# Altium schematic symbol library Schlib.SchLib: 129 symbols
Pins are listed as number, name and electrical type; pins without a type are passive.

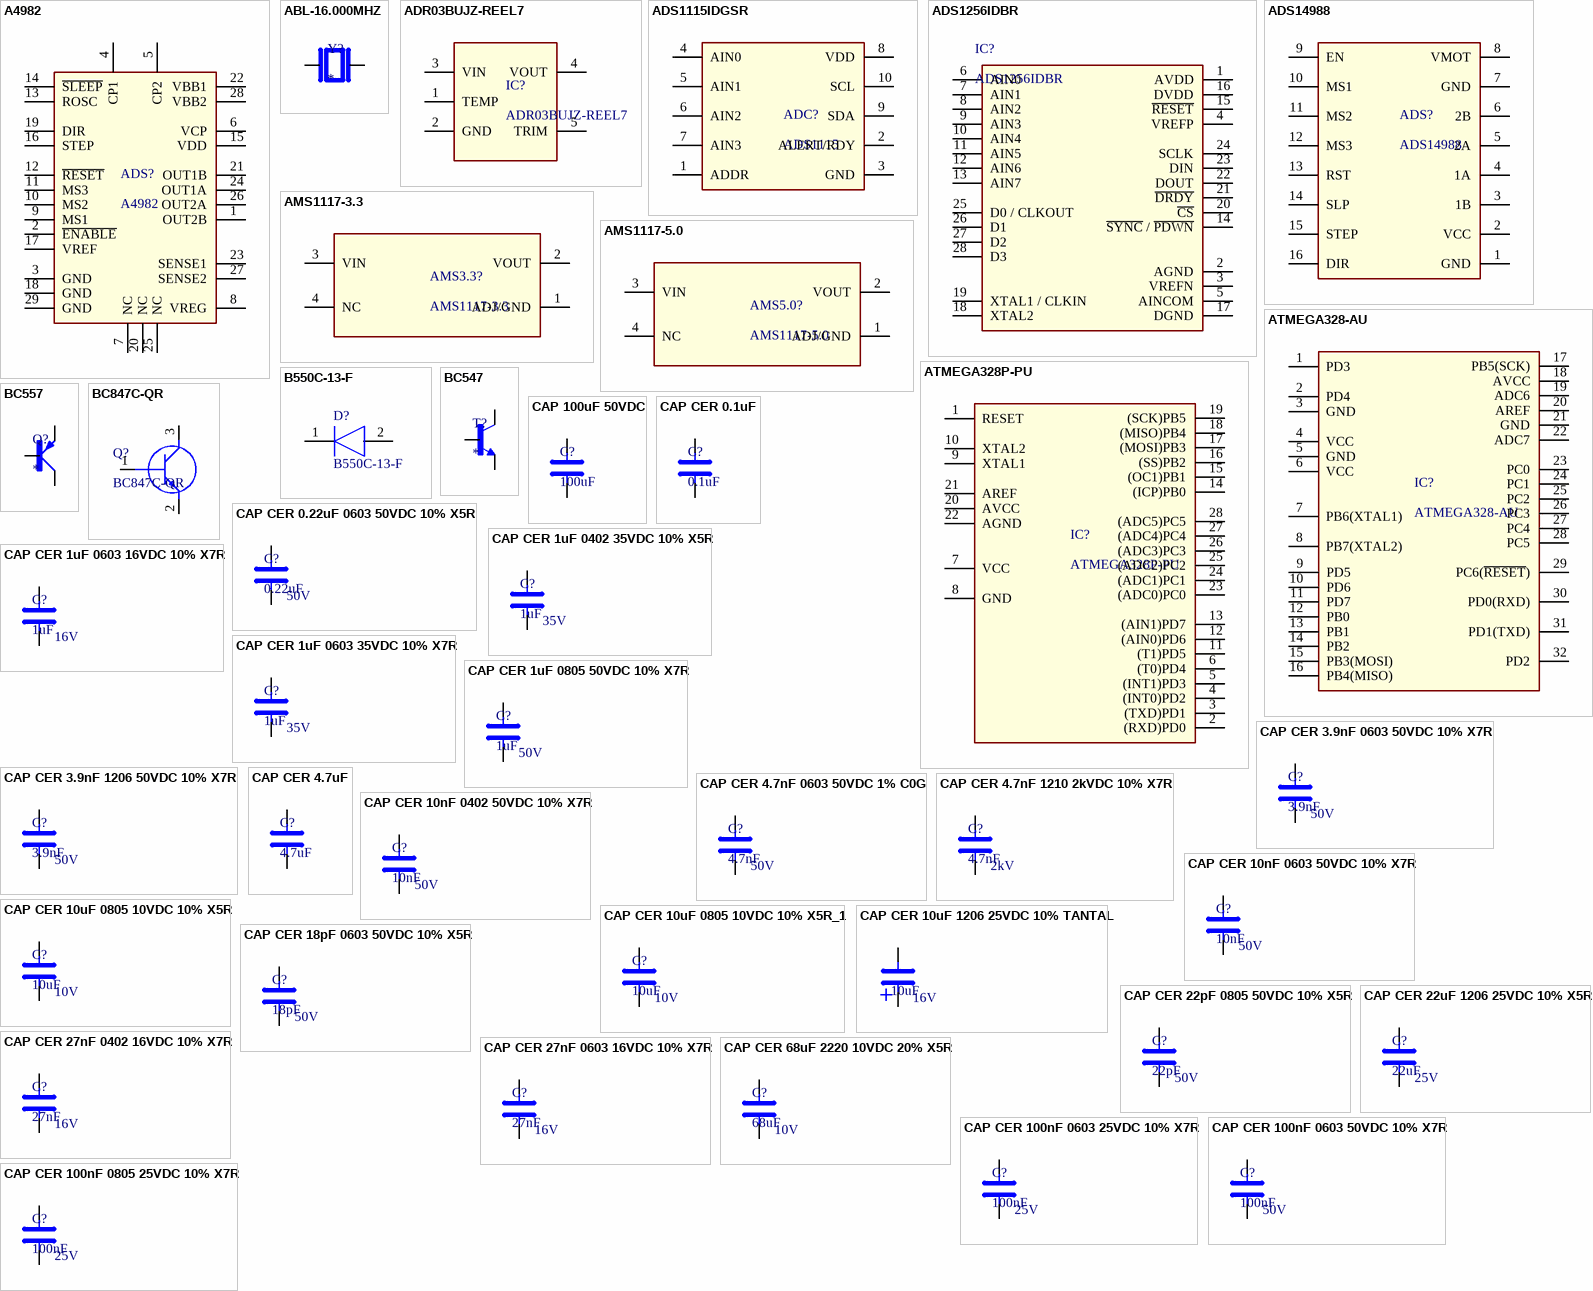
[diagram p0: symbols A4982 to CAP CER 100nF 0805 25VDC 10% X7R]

## A4982
designator ADS?
footprint QFN50P500X500X90-29N
pins: 1 OUT2B, 2 ~{ENABLE}, 3 GND, 4 CP1, 5 CP2, 6 VCP, 7 NC, 8 VREG, 9 MS1, 10 MS2, 11 MS3, 12 ~{RESET}, 13 ROSC, 14 ~{SLEEP}, 15 VDD, 16 STEP, 17 VREF, 18 GND, 19 DIR, 20 NC, 21 OUT1B, 22 VBB1, 23 SENSE1, 24 OUT1A, 25 NC, 26 OUT2A, 27 SENSE2, 28 VBB2, 29 GND

## ABL-16.000MHZ
designator Y?
16 MHz Â±10ppm Crystal 18pF 40 Ohms HC-49/US; MF: Abracon Corporation; MP: ABL-16.000MHZ
footprint XTAL_ABL-16.000MHZ
pins: 1, 2

## ADR03BUJZ-REEL7
designator IC?
2.5V -40℃~+125℃@(TA) ±0.1% 4.5V~36V 10mA 9ppm/℃ Fixed TSOT-23-5 Voltage References ROHS; Manufacturer: Analog Devices
footprint SON65P200X200X80-5N (ADR03BUJZ-REEL7)
pins: 1 TEMP, 2 GND, 3 VIN, 4 VOUT, 5 TRIM

## ADS1115IDGSR
designator ADC?, comment ADS1115
VSSOP-10 Analog To Digital Converters (ADCs) ROHS; Manufacturer: Texas Instruments; Manufacturer Part Number: ADS1115IDGSR
footprint SOP50P490X110-10N
pins: 1 ADDR, 2 ALERT/RDY, 3 GND, 4 AIN0, 5 AIN1, 6 AIN2, 7 AIN3, 8 VDD, 9 SDA, 10 SCL

## ADS1256IDBR
designator IC?
SSOP-28_208mil Analog To Digital Converters (ADCs) ROHS; Manufacturer: Texas Instruments
footprint SOP65P780X200-28N
pins: 1 AVDD, 2 AGND, 3 VREFN, 4 VREFP, 5 AINCOM, 6 AIN0, 7 AIN1, 8 AIN2, 9 AIN3, 10 AIN4, 11 AIN5, 12 AIN6, 13 AIN7, 14 ~{SYNC} / ~{PDWN}, 15 ~{RESET}, 16 DVDD, 17 DGND, 18 XTAL2, 19 XTAL1 / CLKIN, 20 ~{CS}, 21 ~{DRDY}, 22 DOUT, 23 DIN, 24 SCLK, 25 D0 / CLKOUT, 26 D1, 27 D2, 28 D3

## ADS14988
designator ADS?
pins: 1 GND, 2 VCC, 3 1B, 4 1A, 5 2A, 6 2B, 7 GND, 8 VMOT, 9 EN, 10 MS1, 11 MS2, 12 MS3, 13 RST, 14 SLP, 15 STEP, 16 DIR

## AMS1117-3.3
designator AMS3.3?
pins: 1 ADJ/GND, 2 VOUT, 3 VIN, 4 NC

## AMS1117-5.0
designator AMS5.0?
pins: 1 ADJ/GND, 2 VOUT, 3 VIN, 4 NC

## ATMEGA328-AU
designator IC?
footprint QFP80P900X900X120-32N
pins: 1 PD3, 2 PD4, 3 GND, 4 VCC, 5 GND, 6 VCC, 7 PB6(XTAL1), 8 PB7(XTAL2), 9 PD5, 10 PD6, 11 PD7, 12 PB0, 13 PB1, 14 PB2, 15 PB3(MOSI), 16 PB4(MISO), 17 PB5(SCK), 18 AVCC, 19 ADC6, 20 AREF, 21 GND, 22 ADC7, 23 PC0, 24 PC1, 25 PC2, 26 PC3, 27 PC4, 28 PC5, 29 PC6(~{RESET}), 30 PD0(RXD), 31 PD1(TXD), 32 PD2

## ATMEGA328P-PU
designator IC?
pins: 1 RESET, 2 (RXD)PD0, 3 (TXD)PD1, 4 (INT0)PD2, 5 (INT1)PD3, 6 (T0)PD4, 7 VCC, 8 GND, 9 XTAL1, 10 XTAL2, 11 (T1)PD5, 12 (AIN0)PD6, 13 (AIN1)PD7, 14 (ICP)PB0, 15 (OC1)PB1, 16 (SS)PB2, 17 (MOSI)PB3, 18 (MISO)PB4, 19 (SCK)PB5, 20 AVCC, 21 AREF, 22 AGND, 23 (ADC0)PC0, 24 (ADC1)PC1, 25 (ADC2)PC2, 26 (ADC3)PC3, 27 (ADC4)PC4, 28 (ADC5)PC5

## B550C-13-F
designator D?
Schottky Diodes & Rectifiers 50V 5A; Manufacturer: Diodes Inc.; Vf - Forward Voltage: 575mV
footprint DIOAD1950W125L950D560
pins: 1, 2

## BC547
designator T?
Trans GP BJT NPN 45V 0.1A 500mW 3-Pin TO-92 T/R; MP: BC547; MF: ON Semiconductor
footprint TO92250P510H770-3
pins: B, C, E

## BC557
designator Q?
Bipolar (BJT) Transistor PNP 45 V 100 mA 320MHz 625 mW Through Hole TO-92 (TO-226); MP: BC557; MF: ON
footprint SOT54A
pins: B, C, E

## BC847C-QR
designator Q?
Bipolar Transistors - BJT BC847C-Q/SOT23/TO-236AB; Manufacturer: Nexperia; Polarity: NPN; Vsat: 200mV; Iout: 100mA
footprint SOT95P230X110-3N
pins: 1 B, 2 E, 3 C

## CAP 100uF 50VDC
designator C?, comment 100uF
CAP CER 100uF 50v 8mm High Capacitors (493-3289-ND) ovo je potrebno
pins: 1, 2

## CAP CER 0.1uF
designator C?, comment 0.1uF
CAP CER 0.1uF
pins: 1, 2

## CAP CER 0.22uF 0603 50VDC 10% X5R
designator C?, comment 0.22uF  Voltage: 50V
CAP CER 0.22uF 0603 50VDC 10% X5R; Manufacturer: YAGEO; Manufacturer Part Number: CC0603JRNPO9BN180
pins: 1, 2

## CAP CER 1uF 0402 35VDC 10% X5R
designator C?, comment 1uF  Voltage: 35V
CAP CER 1uF 0402 35VDC 10% X5R; Manufacturer: Samsung Electro-Mechanics; Manufacturer Part Number: CL05A105KL5NRNC
footprint CAPC1005X65N (0402)
pins: 1, 2

## CAP CER 1uF 0603 16VDC 10% X7R
designator C?, comment 1uF  Voltage: 16V
CAP CER 1uF 0603 16VDC 10% X7R; Manufacturer: Taiyo Yuden; Manufacturer Part Number: EMK107B7105KA-T
footprint CAPC1608X90N (0603)
pins: 1, 2

## CAP CER 1uF 0603 35VDC 10% X7R
designator C?, comment 1uF  Voltage: 35V
CAP CER 1uF 0603 35VDC 10% X7R; Manufacturer: TDK
footprint CAPC1608X90N (0603)
pins: 1, 2

## CAP CER 1uF 0805 50VDC 10% X7R
designator C?, comment 1uF  Voltage: 50V
CAP CER 1uF 0805 50VDC 10% X7R; Manufacturer: Samsung Electro-Mechanics; Manufacturer Part Number: CL21B105KBFNNNE
footprint CAPC2012X95N (0805)
pins: 1, 2

## CAP CER 3.9nF 0603 50VDC 10% X7R
designator C?, comment 3.9nF  Voltage: 50V
CAP CER 3.9nF 0603 50VDC 10% X7R; Manufacturer: YAGEO; Manufacturer Part Number: CC0603KRX7R9BB392
footprint CAPC1608X90N (0603)
pins: 1, 2

## CAP CER 3.9nF 1206 50VDC 10% X7R
designator C?, comment 3.9nF  Voltage: 50V
CAP CER 3.9nF 1206 50VDC 10% X7R; Manufacturer: CCTC; Manufacturer Part Number: TCC1206X7R392K500DT
footprint CAPC3316X180N (1206)
pins: 1, 2

## CAP CER 4.7nF 0603 50VDC 1% C0G
designator C?, comment 4.7nF  Voltage: 50V
CAP CER 4.7nF 0603 50VDC 1% C0G; Manufacturer: KEMET; Manufacturer Part Number: C0603C472F5GACTU
footprint CAPC1608X90N (0603)
pins: 1, 2

## CAP CER 4.7nF 1210 2kVDC 10% X7R
designator C?, comment 4.7nF  Voltage: 2kV
CAP CER 4.7nF 1210 2kVDC 10% X7R; Manufacturer: Johanson Dielectrics; Manufacturer Part Number: 202S41W472KV4E
footprint CAPC3224X203N
pins: 1, 2

## CAP CER 4.7uF
designator C?, comment 4.7uF
CAP CER 4.7uF
pins: 1, 2

## CAP CER 10nF 0402 50VDC 10% X7R
designator C?, comment 10nF  Voltage: 50V
CAP CER 10nF 0402 50VDC 10% X7R; Manufacturer: Murata Electronics; Manufacturer Part Number: GRM155R71H103KA88D
footprint CAPC1005X65N (0402)
pins: 1, 2

## CAP CER 10nF 0603 50VDC 10% X7R
designator C?, comment 10nF  Voltage: 50V
CAP CER 10nF 0603 50VDC 10% X7R; Manufacturer: YAGEO; Manufacturer Part Number: CC0603KRX7R9BB103
footprint CAPC1608X90N (0603)
pins: 1, 2

## CAP CER 10uF 0805 10VDC 10% X5R
designator C?, comment 10uF  Voltage: 10V
CAP CER 10uF 0805 10VDC 10% X5R; Manufacturer: Samsung Electro-Mechanics; Manufacturer Part Number: CL21A106KPFNNNE
footprint CAPC2012X95N (0805)
pins: 1, 2

## CAP CER 10uF 0805 10VDC 10% X5R_1
designator C?, comment 10uF  Voltage: 10V
CAP CER 10uF 0805 10VDC 10% X5R; Manufacturer: Samsung Electro-Mechanics; Manufacturer Part Number: CL10A106KP8NNNC
footprint CAPC2012X95N (0805)
pins: 1, 2

## CAP CER 10uF 1206 25VDC 10% TANTAL
designator C?, comment 10uF  Voltage: 16V
CAP CER 10uF 1206 16VDC 10% TANTAL; Manufacturer: Kyocera AVX; Manufacturer Part Number: TAJA106K016RNJ; Dielectric: Tantalum
footprint CAPPM3216X180N
pins: 1, 2

## CAP CER 18pF 0603 50VDC 10% X5R
designator C?, comment 18pF  Voltage: 50V
CAP CER 18pF 0603 50VDC 10% X5R; Manufacturer: YAGEO; Manufacturer Part Number: CC0603JRNPO9BN180
footprint CAPC1608X90N (0603)
pins: 1, 2

## CAP CER 22pF 0805 50VDC 10% X5R
designator C?, comment 22pF  Voltage: 50V
CAP CER 22pF 0805 50VDC 10% X5R; Manufacturer: Samsung Electro-Mechanics; Manufacturer Part Number: CL10A106KP8NNNC
footprint CAPC2012X95N (0805)
pins: 1, 2

## CAP CER 22uF 1206 25VDC 10% X5R
designator C?, comment 22uF  Voltage: 25V
CAP CER 22uF 1206 25VDC 10% X5R; Manufacturer: Samsung Electro-Mechanics; Manufacturer Part Number: CL31A226KAHNNNE
footprint CAPC3316X180N (1206)
pins: 1, 2

## CAP CER 27nF 0402 16VDC 10% X7R
designator C?, comment 27nF  Voltage: 16V
CAP CER 27nF 0402 16VDC 10% X7R; Manufacturer: Murata Electronics; Manufacturer Part Number: GRM155R71C273KA01D
footprint CAPC1005X65N (0402)
pins: 1, 2

## CAP CER 27nF 0603 16VDC 10% X7R
designator C?, comment 27nF  Voltage: 16V
CAP CER 27nF 0603 16VDC 10% X7R; Manufacturer: YAGEO; Manufacturer Part Number: CC0603JRX7R7BB273
footprint CAPC1608X90N (0603)
pins: 1, 2

## CAP CER 68uF 2220 10VDC 20% X5R
designator C?, comment 68uF  Voltage: 10V
CAP CER 68uF 2220 10VDC 20% X5R; Manufacturer: TDK; Manufacturer Part Number: C5750X5R1A686MT000N
footprint C2220
pins: 1, 2

## CAP CER 100nF 0603 25VDC 10% X7R
designator C?, comment 100nF  Voltage: 25V
CAP CER 100nF 0603 25VDC 10% X7R; Manufacturer: Samsung Electro-Mechanics; Manufacturer Part Number: CL10B104KA8NNNC
footprint CAPC1608X90N (0603)
pins: 1, 2

## CAP CER 100nF 0603 50VDC 10% X7R
designator C?, comment 100nF  Voltage: 50V
CAP CER 100nF 0603 50VDC 10% X7R; Manufacturer: Samsung Electro-Mechanics; Manufacturer Part Number: CL10B104KB8NNWC
footprint CAPC1608X90N (0603)
pins: 1, 2

## CAP CER 100nF 0805 25VDC 10% X7R
designator C?, comment 100nF  Voltage: 25V
CAP CER 100nF 0805 25VDC 10% X7R; Manufacturer: YAGEO; Manufacturer Part Number: CC0805KRX7R8BB104
footprint CAPC2012X95N (0805)
pins: 1, 2

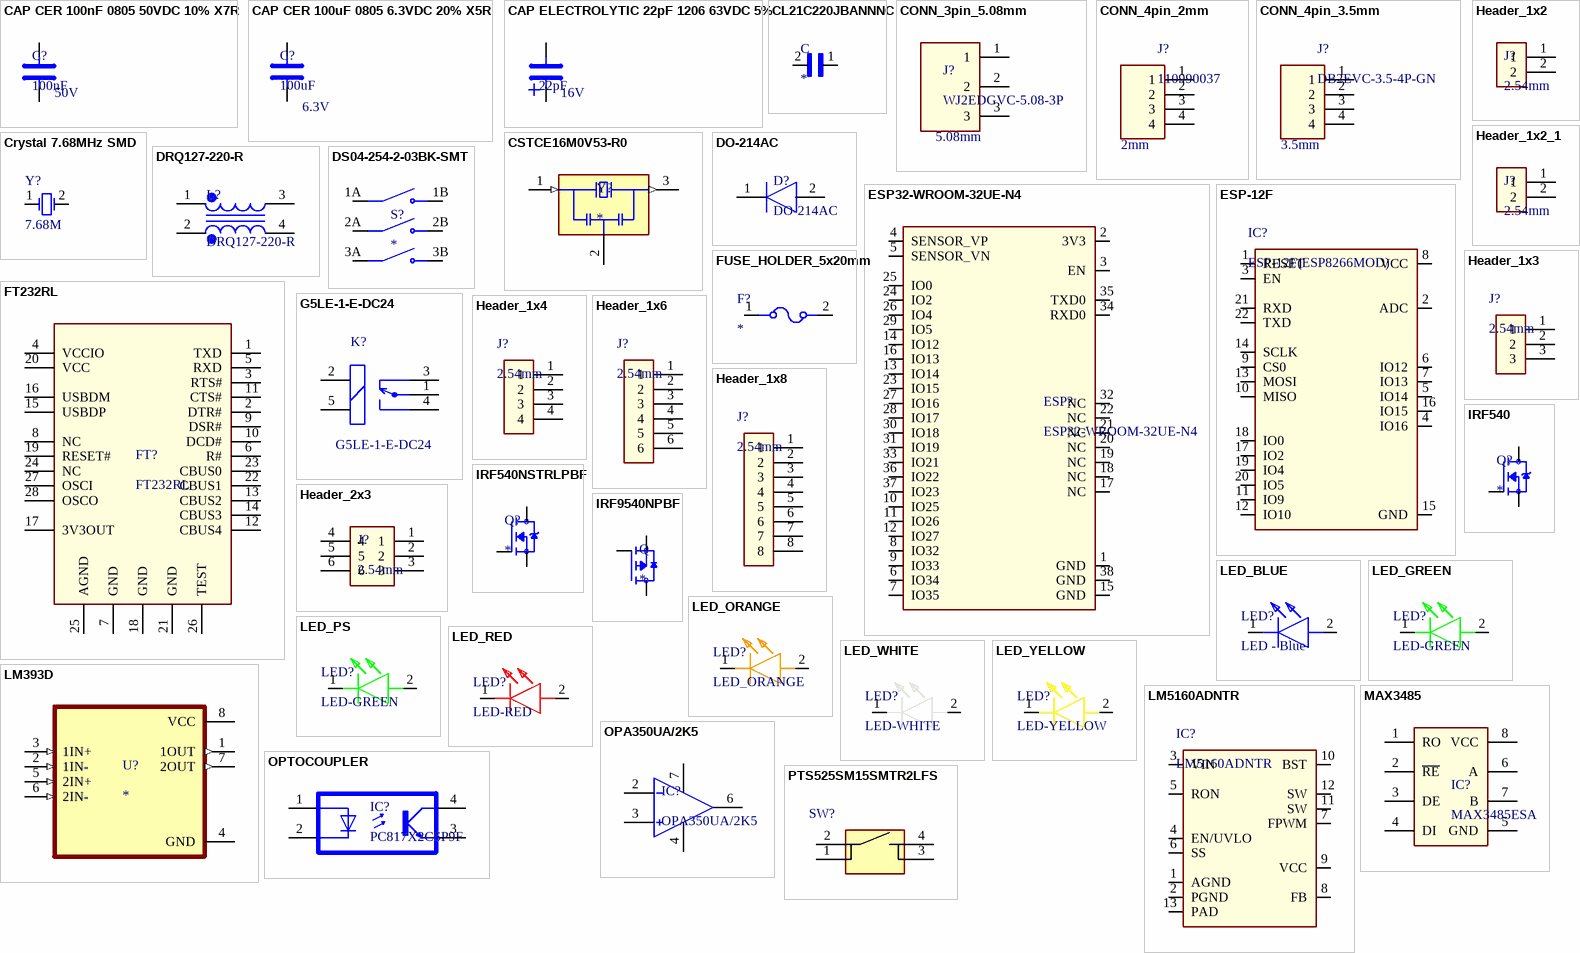
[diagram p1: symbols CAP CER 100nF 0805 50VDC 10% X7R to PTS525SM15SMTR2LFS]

## CAP CER 100nF 0805 50VDC 10% X7R
designator C?, comment 100nF  Voltage: 50V
CAP CER 100nF 0805 50VDC 10% X7R; Manufacturer: Samsung Electro-Mechanics; Manufacturer Part Number: CL21B104KBFNNNE
footprint CAPC2012X95N (0805)
pins: 1, 2

## CAP CER 100uF 0805 6.3VDC 20% X5R
designator C?, comment 100uF  Voltage: 6.3V
CAP CER 100uF 0805 6.3VDC 20% X5R; Manufacturer: Taiyo Yuden; Manufacturer Part Number: JMK212BBJ107MG-TE
footprint CAPC2012X95N (0805)
pins: 1, 2

## CAP ELECTROLYTIC 22pF 1206 63VDC 5%
designator C?, comment 22pF  Voltage: 16V
CAP ELECTROLYTIC 22pF 1206 63VDC 5%; Manufacturer: Kyocera AVX; Manufacturer Part Number: TAJA106K016RNJ; Dielectric: Tantalum
footprint CAPPM3216X180N
pins: 1, 2

## CL21C220JBANNNC
designator C
22pF Â±5% 50V Ceramic Capacitor C0G, NP0 0805 _2012 Metric_; MF: Samsung; MP: CL21C220JBANNNC
footprint CAPC2012X140N
pins: 1, 2

## CONN_3pin_5.08mm
designator J?, comment WJ2EDGVC-5.08-3P  Pitch: 5.08mm
3 Straight pin 1 5.08mm Green Board Edge/Receptacle-Close Straight,P=5.08mm Pluggable System Terminal Block ROHS; Manufacturer: Ningbo Kangnex Elec
pins: 1, 2, 3

## CONN_4pin_2mm
designator J?, comment 110990037  Pitch: 2mm
GROVE 2MM 4PIN R/A CONN 10PACK; Manufacturer: Seeed Technology Co., Ltd
footprint CONN_2MM_4PIN
pins: 1, 2, 3, 4

## CONN_4pin_3.5mm
designator J?, comment DB2EVC-3.5-4P-GN  Pitch: 3.5mm
300V 8A 4 Straight pin -40℃~+105℃ 1 3.5mm Green Board Edge/Receptacle-Close Plugin,P=3.5mm Pluggable System Terminal Block ROHS; Manufacturer: DIBO
pins: 1, 2, 3, 4

## Crystal 7.68MHz SMD
designator Y?, comment 7.68M
Suzhou Liming Elec 49MD-7.680-18-10-10/B
footprint LFXTAL061856Reel
pins: 1 OSC1, 2 OSC2

## CSTCE16M0V53-R0
designator Y?
16 MHz Ceramic Resonator Built in Capacitor 15 pF Â±0.3% -20Â°C ~ 80Â°C Surface Mount; MF: Murata; MP: CSTCE16M0V53-R0
footprint OSC_CSTCE16M0V53-R0
pins: 1 IN (in), 2 GND (power), 3 OUT (out)

## DO-214AC
designator D?
1A 5uA@1kV 1kV 1.1V@1A SMA(DO-214AC) Diodes - General Purpose ROHS; Manufacturer: MDD（Microdiode Electronics）; Manufacturer Part Number: M7
footprint DIOM5227X270N
pins: 1 K, 2 A

## DRQ127-220-R
designator L?
Common Mode Chokes / Filters WE-CNSW 0805 370mA 90Ohm 100MHz AECQ2; Manufacturer: Coiltronics / Eaton
footprint INDM125125X800-4N
pins: 1 (power), 2 (power), 3 (power), 4 (power)

## DS04-254-2-03BK-SMT
designator S?
DS05-127-2-04BK-SMT-TR; MF: {'manufacturer': u'CUI'}; MP: DS04-254-2-03BK-SMT
footprint SW_DS04-254-2-03BK-SMT
pins: 1A COM1, 1B NO1, 2A COM2, 2B NO2, 3A COM3, 3B NO3

## ESP32-WROOM-32UE-N4
designator ESP?
Multiprotocol Modules SMD module ESP32-WROOM-32UE, ESP32-D0WD-V3, ESP32 ECO V3, 4 MB SPI flash, IPEX antenna connector; Manufacturer: Espressif Systems
footprint ESP32WROOM32UE
pins: 1 GND, 2 3V3, 3 EN, 4 SENSOR_VP, 5 SENSOR_VN, 6 IO34, 7 IO35, 8 IO32, 9 IO33, 10 IO25, 11 IO26, 12 IO27, 13 IO14, 14 IO12, 15 GND, 16 IO13, 17 NC, 18 NC, 19 NC, 20 NC, 21 NC, 22 NC, 23 IO15, 24 IO2, 25 IO0, 26 IO4, 27 IO16, 28 IO17, 29 IO5, 30 IO18, 31 IO19, 32 NC, 33 IO21, 34 RXD0, 35 TXD0, 36 IO22, 37 IO23, 38 GND

## ESP-12F
designator IC?, comment ESP-12F(ESP8266MOD)
-90dBm 16dBm ESP8266 PCB On Board Antenna 2.4GHz WIFI Module WiFi Modules ROHS; Manufacturer: Ai-Thinker; Operating Voltage: 3.3V
footprint ESP-12F
pins: 1 RESET, 2 ADC, 3 EN, 4 IO16, 5 IO14, 6 IO12, 7 IO13, 8 VCC, 9 CS0, 10 MISO, 11 IO9, 12 IO10, 13 MOSI, 14 SCLK, 15 GND, 16 IO15, 17 IO2, 18 IO0, 19 IO4, 20 IO5, 21 RXD, 22 TXD

## FT232RL
designator FT?
USB Interface IC USB to Serial UART Enhanced IC SSOP-28
pins: 1 TXD, 2 DTR#, 3 RTS#, 4 VCCIO, 5 RXD, 6 R#, 7 GND, 8 NC, 9 DSR#, 10 DCD#, 11 CTS#, 12 CBUS4, 13 CBUS2, 14 CBUS3, 15 USBDP, 16 USBDM, 17 3V3OUT, 18 GND, 19 RESET#, 20 VCC, 21 GND, 22 CBUS1, 23 CBUS0, 24 NC, 25 AGND, 26 TEST, 27 OSCI, 28 OSCO

## FUSE_HOLDER_5x20mm
designator F?
Manufacturer: XFCN; Manufacturer Part Number: PTF-77
footprint 0PTF0078P
pins: 1, 2

## G5LE-1-E-DC24
designator K?
Relay or Contactor; Manufacturer: Omron Electronics
footprint G5LE1EDC12
pins: 1 COM, 2 COIL_1, 3 NO, 4 NC, 5 COIL_2

## Header_1x2
designator J?, comment 2.54mm
Male Header 1x2
pins: 1, 2

## Header_1x2_1
designator J?, comment 2.54mm
Female Header 1x2
pins: 1, 2

## Header_1x3
designator J?, comment 2.54mm
Male Header 1x3
pins: 1, 2, 3

## Header_1x4
designator J?, comment 2.54mm
Male Header 1x4; Manufacturer: Ckmtw(Shenzhen Cankemeng); Manufacturer Part Number: B-2100S04P-A110; Number of Positions: 4
footprint HEADER1X4
pins: 1, 2, 3, 4

## Header_1x6
designator J?, comment 2.54mm
Female Header 1x6; Manufacturer: MOLEX; Manufacturer Part Number: 0901471106; Number of Positions: 6
footprint HEADER1X6
pins: 1, 2, 3, 4, 5, 6

## Header_1x8
designator J?, comment 2.54mm
Male Header 1x8                                3A Straight Square Pins 2.5mm 6mm; Manufacturer: HCTL; Manufacturer Part Number: PZ254-1-08-Z-8.5; Number of Positions: 8
footprint HEADER1X8
pins: 1, 2, 3, 4, 5, 6, 7, 8

## Header_2x3
designator J?, comment 2.54mm
Male Header 2x3
pins: 1, 2, 3, 4, 5, 6

## IRF540
designator Q?
N-Channel 100V 22A (Tc) 85W (Tc) Through Hole TO-220AB; MP: IRF540
footprint TO254P1052X465X1989-3
pins: 1 G, 2 D, 3 S

## IRF540NSTRLPBF
designator Q?
MOSFET, Power; N-Ch; VDSS 100V; RDS(ON) 44Milliohms; ID 33A; D2Pak; PD 130W; VGS +/-20; MF: Infineon Technologies; MP: IRF540NSTRLPBF
footprint TO254P1052X465X1989-3
pins: 1 G, 2 D, 3 S

## IRF9540NPBF
designator Q
RoHS Compliant ¦ Low RDS(on) ¦ Industry-leading quality ¦ Dynamic dv/dt Rating ¦ Fast Switching ¦ Fully Avalanche Rated ¦ 175C Operating Temperature ¦ P-Channel MOSFET; MP: IRF9540NPBF; MF: Infineon Technologies
footprint TO254P1052X465X1989-3
pins: 1 G, 2 D, 3 S

## LED_BLUE
designator LED?, comment LED - Blue
5mA 468nm Colorless transparence -40℃~+85℃ 465nm~475nm blue 120° 110mW 0603 Light Emitting Diodes (LED) ROHS; Manufacturer: Everlight Elec; Manufacturer Part Number: 19-217/BHC-ZL1M2RY/3T
footprint LEDM168X65N_BLUE
pins: 1 K, 2 A

## LED_GREEN
designator LED?, comment LED-GREEN
20mA 518nm Colorless transparence -40℃~+85℃ 520nm~535nm Emerald 120° 110mW 0603 Light Emitting Diodes (LED) ROHS; Manufacturer: Everlight Elec; Manufacturer Part Number: 19-217/GHC-YR1S2/3T; Colour: Brilliant Green
footprint LEDM168X65N_GREEN
pins: 1 K, 2 A

## LED_ORANGE
designator LED?
Standard LEDs - SMD Orange 605nm 100mcd Vf 2.2V Pd 54mW; Manufacturer: ROHM Semiconductor; Manufacturer Part Number: SML-D12D1WT86; Forward Current: 20mA
footprint LEDM168X65N_ORANGE
pins: 1 K, 2 A

## LED_PS
designator LED?, comment LED-GREEN
Standard LEDs - SMD MINI-MOLD SMD LED GREEN; Manufacturer: ROHM Semicon; Manufacturer Part Number: SMLD12EN1WT86; Forward Voltage: 3V; Forward Current: 5mA
footprint LEDM168X65N_GREEN
pins: 1, 2

## LED_RED
designator LED?, comment LED-RED
5mA 632nm Colorless transparence -40℃~+85℃ 617.5nm~633.5nm Red 120° 60mW 0603 Light Emitting Diodes (LED) ROHS; Manufacturer: Everlight Elec; Manufacturer Part Number: 19-217/R6C-AL1M2VY/3T
footprint LEDM168X65N_RED
pins: 1 K, 2 A

## LED_WHITE
designator LED?, comment LED-WHITE
White light 0603 Light Emitting Diodes (LED) ROHS; Manufacturer: Foshan NationStar Optoelectronics; Manufacturer Part Number: NCD0603W3
footprint LEDM168X65N_WHITE
pins: 1 K, 2 A

## LED_YELLOW
designator LED?, comment LED-YELLOW
20mA 591nm Colorless transparence -40℃~+85℃ 585.5nm~591.5nm yellow 120° 60mW 0603 Light Emitting Diodes (LED) ROHS; Manufacturer: Everlight Elec; Manufacturer Part Number: 19-213/Y2C-CQ2R2L/3T(CY)
footprint LEDM168X65N_YELLOW
pins: 1 K, 2 A

## LM393D
designator U?
Dual differential comparator, commercial grade; MP: LM393D; MF: Texas Instruments
footprint SOIC127P599X175-8N
pins: 1 1OUT (out), 2 1IN- (in), 3 1IN+ (in), 4 GND (power), 5 2IN+ (in), 6 2IN- (in), 7 2OUT (out), 8 VCC (power)

## LM5160ADNTR
designator IC?
Switching Voltage Regulators Wide Input 65V 1.5A Synch Buck; Manufacturer: Texas Instruments; Iout: 2A
footprint SON50P400X400X80-13N
pins: 1 AGND, 2 PGND, 3 VIN, 4 EN/UVLO, 5 RON, 6 SS, 7 FPWM, 8 FB, 9 VCC, 10 BST, 11 SW, 12 SW, 13 PAD

## MAX3485
designator IC?, comment MAX3485ESA
SOP-8 RS-485/RS-422 ICs ROHS; Manufacturer: TWGMC
footprint SOIC127P600X175-8N
pins: 1 RO, 2 ~{RE}, 3 DE, 4 DI, 5 GND, 6 A, 7 B, 8 VCC

## OPA350UA/2K5
designator IC?
38MHz 1 SOIC-8 Precision OpAmps ROHS; Manufacturer: Texas Instruments
footprint SOIC127P600X175-8N
pins: 2 (power), 3 (power), 4 GND (power), 6 (power), 7 VCC (power)

## OPTOCOUPLER
designator IC?, comment PC817X2CSP9F
80V 5000V -30℃~+100℃ 4us@2mA,100Ω 50mA 3us@2mA,100Ω 0.1V@1mA,20mA 1 6V 1.2V Phototransistor DC SMD-4 Optocouplers - Phototransistor Output ROHS; Manufacturer: Sharp Microelectronics
footprint OPTOCOUPLER
pins: 1, 2, 3, 4

## PTS525SM15SMTR2LFS
designator SW?  (value not drawn)
Tactile Switches 20mA 15VDC, G Lead No Pin, 160gf, 1.5mm; Manufacturer: C&K
footprint PTS525SM08SMTR2LFS
pins: 1, 2, 3, 4

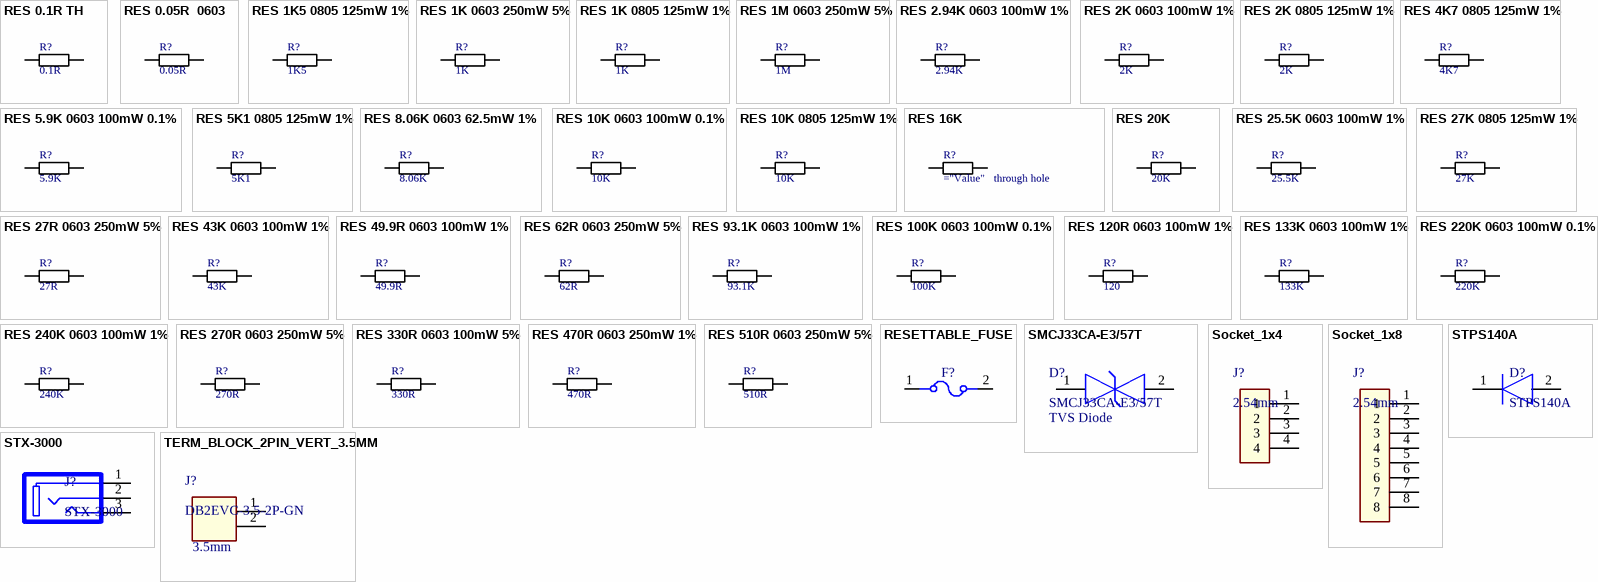
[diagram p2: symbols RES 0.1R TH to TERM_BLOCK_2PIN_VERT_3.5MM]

## RES 0.1R TH
designator R?, comment 0.1R
RES 0.1R TH
footprint RESAD1100W55L680D260
pins: 1, 2

## RES 0.05R  0603
designator R?, comment 0.05R
RES 0.05R  0603
pins: 1, 2

## RES 1K5 0805 125mW 1%
designator R?, comment 1K5
RES 1K5 0805 125mW 1%; Manufacturer: UNI-ROYAL(Uniroyal Elec); Manufacturer Part Number: 0805W8F1501T5E
footprint RESC2012X60N
pins: 1, 2

## RES 1K 0603 250mW 5%
designator R?, comment 1K
RES 100K 0603 250mW 5%; Manufacturer: Panasonic; Manufacturer Part Number: ERJ-PA3J102V
footprint RESC1608X55N
pins: 1, 2

## RES 1K 0805 125mW 1%
designator R?, comment 1K
RES 1K 0805 125mW 1%; Manufacturer: UNI-ROYAL(Uniroyal Elec); Manufacturer Part Number: 0805W8F1001T5E
footprint RESC2012X60N
pins: 1, 2

## RES 1M 0603 250mW 5%
designator R?, comment 1M
RES 1M 0603 250mW 5%; Manufacturer: Panasonic; Manufacturer Part Number: ERJ-PA3J511V
footprint RESC1608X55N
pins: 1, 2

## RES 2.94K 0603 100mW 1%
designator R?, comment 2.94K
RES 2.94K 0603 100mW 1%; Manufacturer: FOJAN; Manufacturer Part Number: FRC0603F2941TS
footprint RESC1608X55N
pins: 1, 2

## RES 2K 0603 100mW 1%
designator R?, comment 2K
RES 2K 0603 100mW 1%; Manufacturer: YAGEO; Manufacturer Part Number: RC0603FR-072KL
footprint RESC1608X55N
pins: 1, 2

## RES 2K 0805 125mW 1%
designator R?, comment 2K
RES 2K 0805 125mW 1%; Manufacturer: UNI-ROYAL(Uniroyal Elec); Manufacturer Part Number: 0805W8F2001T5E
footprint RESC2012X60N
pins: 1, 2

## RES 4K7 0805 125mW 1%
designator R?, comment 4K7
RES 4K7 0805 125mW 1%; Manufacturer: UNI-ROYAL(Uniroyal Elec); Manufacturer Part Number: 0805W8F4701T5E
footprint RESC2012X60N
pins: 1, 2

## RES 5.9K 0603 100mW 0.1%
designator R?, comment 5.9K
RES 5.9K 0603 100mW 0.1%; Manufacturer: YAGEO; Manufacturer Part Number: RT0603BRD075K9L
footprint RESC1608X55N
pins: 1, 2

## RES 5K1 0805 125mW 1%
designator R?, comment 5K1
RES 5K1 0805 125mW 1%; Manufacturer: UNI-ROYAL(Uniroyal Elec); Manufacturer Part Number: 0805W8F4701T5E
footprint RESC2012X60N
pins: 1, 2

## RES 8.06K 0603 62.5mW 1%
designator R?, comment 8.06K
RES 8.06K 0603 62.5mW 1%; Manufacturer: Viking Tech; Manufacturer Part Number: AR03BTC8061
footprint RESC1608X55N
pins: 1, 2

## RES 10K 0603 100mW 0.1%
designator R?, comment 10K
RES 10K 0603 100mW 0.1%; Manufacturer: YAGEO; Manufacturer Part Number: RT0603BRE0710KL
footprint RESC1608X55N
pins: 1, 2

## RES 10K 0805 125mW 1%
designator R?, comment 10K
RES 10K 0805 125mW 1%; Manufacturer: UNI-ROYAL(Uniroyal Elec); Manufacturer Part Number: 0805W8F1002T5E
footprint RESC2012X60N
pins: 1, 2

## RES 16K
designator R?
RES 16K
pins: 1, 2

## RES 20K
designator R?, comment 20K
RES 20K
pins: 1, 2

## RES 25.5K 0603 100mW 1%
designator R?, comment 25.5K
RES 25.5K 0603 100mW 1%; Manufacturer: FOJAN; Manufacturer Part Number: FRC0603F2552TS
footprint RESC1608X55N
pins: 1, 2

## RES 27K 0805 125mW 1%
designator R?, comment 27K
RES 27K 0805 125mW 1%
footprint RESC2012X60N
pins: 1, 2

## RES 27R 0603 250mW 5%
designator R?, comment 27R
RES 27R 0603 250mW 5%; Manufacturer: ROHM Semiconductor; Manufacturer Part Number: ESR03EZPJ270
footprint RESC1608X55N
pins: 1, 2

## RES 43K 0603 100mW 1%
designator R?, comment 43K
RES 43K 0603 100mW 1%; Manufacturer: YAGEO; Manufacturer Part Number: RC0603FR-0743KL
footprint RESC1608X55N
pins: 1, 2

## RES 49.9R 0603 100mW 1%
designator R?, comment 49.9R
RES 49.9R 0603 100mW 1%; Manufacturer: YAGEO; Manufacturer Part Number: RC0603FR-0749R9L
footprint RESC1608X55N
pins: 1, 2

## RES 62R 0603 250mW 5%
designator R?, comment 62R
RES 62R 0603 250mW 5%; Manufacturer: Panasonic; Manufacturer Part Number: ERJ-PA3J620V
footprint RESC1608X55N
pins: 1, 2

## RES 93.1K 0603 100mW 1%
designator R?, comment 93.1K
RES 93.1K 0603 100mW 1%; Manufacturer: FOJAN; Manufacturer Part Number: FRC0603F9312TS
footprint RESC1608X55N
pins: 1, 2

## RES 100K 0603 100mW 0.1%
designator R?, comment 100K
RES 100K 0603 100mW 0.1%; Manufacturer: YAGEO; Manufacturer Part Number: RT0603BRD07100KL
footprint RESC1608X55N
pins: 1, 2

## RES 120R 0603 100mW 1%
designator R?, comment 120
RES 120R 0603 100mW 1%; Manufacturer: YAGEO; Manufacturer Part Number: RC0603FR-07120RL
footprint RESC1608X55N
pins: 1, 2

## RES 133K 0603 100mW 1%
designator R?, comment 133K
RES 133K 0603 100mW 1%; Manufacturer: FOJAN; Manufacturer Part Number: FRC0603F1333TS
footprint RESC1608X55N
pins: 1, 2

## RES 220K 0603 100mW 0.1%
designator R?, comment 220K
RES 220K 0603 100mW 0.1%; Manufacturer: YAGEO; Manufacturer Part Number: RT0603BRD07220KL
footprint RESC1608X55N
pins: 1, 2

## RES 240K 0603 100mW 1%
designator R?, comment 240K
RES 240K 0603 100mW 1%; Manufacturer: Panasonic; Manufacturer Part Number: ERJ3EKF2403V
footprint RESC1608X55N
pins: 1, 2

## RES 270R 0603 250mW 5%
designator R?, comment 270R
RES 270R 0603 250mW 5%; Manufacturer: ROHM Semiconductor; Manufacturer Part Number: ESR03EZPJ271
footprint RESC1608X55N
pins: 1, 2

## RES 330R 0603 100mW 5%
designator R?, comment 330R
RES 330R 0603 100mW 5%; Manufacturer: Panasonic; Manufacturer Part Number: ERJ-3GEYJ331V
footprint RESC1608X55N
pins: 1, 2

## RES 470R 0603 250mW 1%
designator R?, comment 470R
RES 470R 0603 250mW 1%; Manufacturer: YAGEO; Manufacturer Part Number: ESR03EZPF4700
footprint RESC1608X55N
pins: 1, 2

## RES 510R 0603 250mW 5%
designator R?, comment 510R
RES 510R 0603 250mW 5%; Manufacturer: Panasonic; Manufacturer Part Number: ERJ-PA3J511V
footprint RESC1608X55N
pins: 1, 2

## RESETTABLE_FUSE
designator F?, comment MF-SMDF050-2  (value not drawn)
60V 550mA 10A 1.2A 2018 Resettable Fuses ROHS; Manufacturer: BOURNS
footprint FUSC5146X109N
pins: 1, 2

## SMCJ33CA-E3/57T
designator D?  value TVS Diode
ESD Suppressors / TVS Diodes 1500W 33V Bidirect; Manufacturer: Vishay General Semiconductor; Breakdown Voltage: 36.7V; Clamping Voltage: 53.3V
footprint DIONM7959X262N
pins: 1, 2

## Socket_1x4
designator J?, comment 2.54mm
Female Socket 1x4; Manufacturer: ZHOURI; Manufacturer Part Number: PM2.54-1*4; Number of Positions: 4
footprint SOCKET1X4
pins: 1, 2, 3, 4

## Socket_1x8
designator J?, comment 2.54mm
Female Socket 1x8; Manufacturer: BOOMELE(Boom Precision Elec); Manufacturer Part Number: C27438; Number of Positions: 8
footprint SOCKET1X8
pins: 1, 2, 3, 4, 5, 6, 7, 8

## STPS140A
designator D?
Schottky Diodes & Rectifiers 1.0 Amp 40 Volt; Manufacturer: STMicroelectronics
footprint DIOM5226X223N
pins: 1 K, 2 A

## STX-3000
designator J?
CONN JACK STEREO 3.5MM TH R/A; Manufacturer: Kycon, Inc.
footprint STX3000
pins: 1, 2, 3

## TERM_BLOCK_2PIN_VERT_3.5MM
designator J?, comment DB2EVC-3.5-2P-GN  Pitch: 3.5mm
300V 8A 2 Straight pin -40℃~+105℃ 1 3.5mm Green Board Edge/Receptacle-Close Plugin,P=3.5mm Pluggable System Terminal Block ROHS; Manufacturer: DIBO; Number of Positions: 2
footprint 3.5MM_2POS_TERM_BLOCK
pins: 1, 2

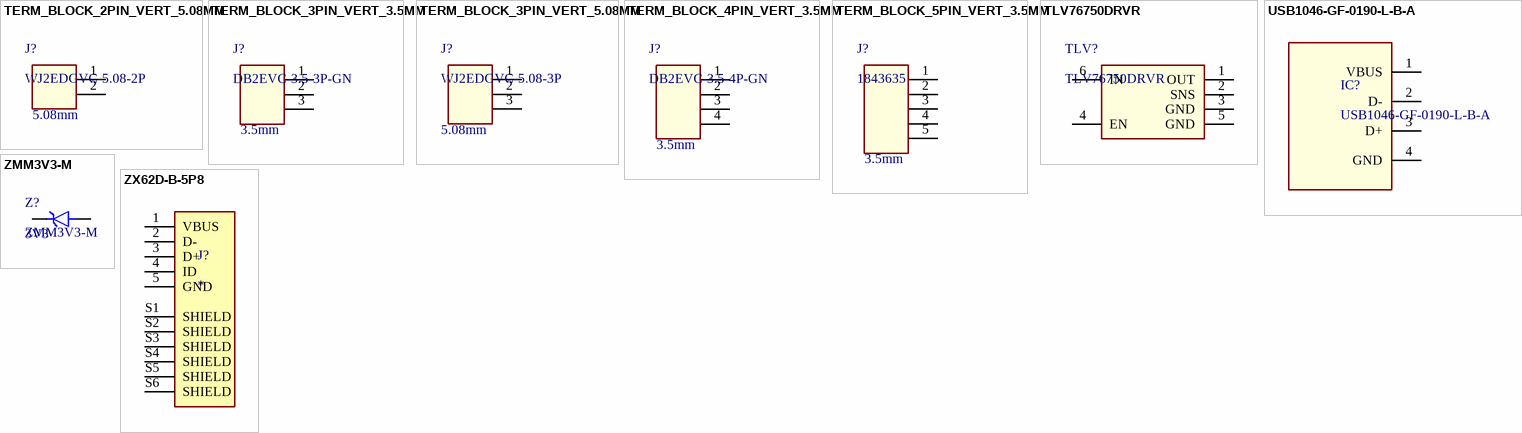
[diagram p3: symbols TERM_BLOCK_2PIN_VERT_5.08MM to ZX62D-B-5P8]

## TERM_BLOCK_2PIN_VERT_5.08MM
designator J?, comment WJ2EDGVC-5.08-2P  Pitch: 5.08mm
2 Straight pin 1 5.08mm Green Board Edge/Receptacle-Close Plugin,P=5.08mm Pluggable System Terminal Block ROHS; Manufacturer: Ningbo Kangnex Elec; Number of Positions: 2
footprint 5MM_2POS_TERM_BLOCK
pins: 1, 2

## TERM_BLOCK_3PIN_VERT_3.5MM
designator J?, comment DB2EVC-3.5-3P-GN  Pitch: 3.5mm
250V 10A 3 Straight pin -40℃~+105℃ 1 3.5mm Green Board Edge/Receptacle-Close Plugin,P=3.5mm Pluggable System Terminal Block ROHS; Manufacturer: DIBO; Number Of Positions: 3
footprint 1843619
pins: 1, 2, 3

## TERM_BLOCK_3PIN_VERT_5.08MM
designator J?, comment WJ2EDGVC-5.08-3P  Pitch: 5.08mm
3 Straight pin 1 5.08mm Green Board Edge/Receptacle-Close Straight,P=5.08mm Pluggable System Terminal Block ROHS; Manufacturer: Ningbo Kangnex Elec; Number of Positions: 3
footprint 5MM_3POS_TERM_BLOCK
pins: 1, 2, 3

## TERM_BLOCK_4PIN_VERT_3.5MM
designator J?, comment DB2EVC-3.5-4P-GN  Pitch: 3.5mm
300V 8A 4 Straight pin -40℃~+105℃ 1 3.5mm Green Board Edge/Receptacle-Close Plugin,P=3.5mm Pluggable System Terminal Block ROHS; Manufacturer: DIBO; Number of Positions: 4
footprint 1843622
pins: 1, 2, 3, 4

## TERM_BLOCK_5PIN_VERT_3.5MM
designator J?, comment 1843635  Pitch: 3.5mm
5 Position Terminal Block Header, Male Pins, Shrouded (4 Side) 0.138" (3.50mm) Vertical Through Hole; Manufacturer: Phoenix Contact; Number Of Positions: 5
footprint 1843635
pins: 1, 2, 3, 4, 5

## TLV76750DRVR
designator TLV?
Linear Voltage Regulator IC Positive Fixed 1 Output 1A 6-WSON (2x2); Manufacturer: Texas Instruments
footprint SON65P200X200X80-7N
pins: 1 OUT, 2 SNS, 3 GND, 4 EN, 5 GND, 6 IN

## USB1046-GF-0190-L-B-A
designator IC?
USB A FEMALE USB1046-GF-0190-L-B-A
footprint SAMTEC_USB-AM-S-X-X-SM1-R
pins: 1 VBUS, 2 D-, 3 D+, 4 GND

## ZMM3V3-M
designator Z?  Voltage: 3V3
2uA@1V 85Ω Single 3.1V~3.5V 500mW 3.3V LL-34 Zener Diodes ROHS; Manufacturer: ST(Semtech)
footprint FDLL4448
pins: 1 K, 2 A

## ZX62D-B-5P8
designator J?
USB - micro B USB 2.0 Receptacle Connector 5 Position Surface Mount, Right Angle; Through Hole; MF: Hirose Connector; MP: ZX62D-B-5P8
footprint HRS_ZX62D-B-5P8
pins: 1 VBUS, 2 D-, 3 D+, 4 ID, 5 GND, S1 SHIELD, S2 SHIELD, S3 SHIELD, S4 SHIELD, S5 SHIELD, S6 SHIELD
